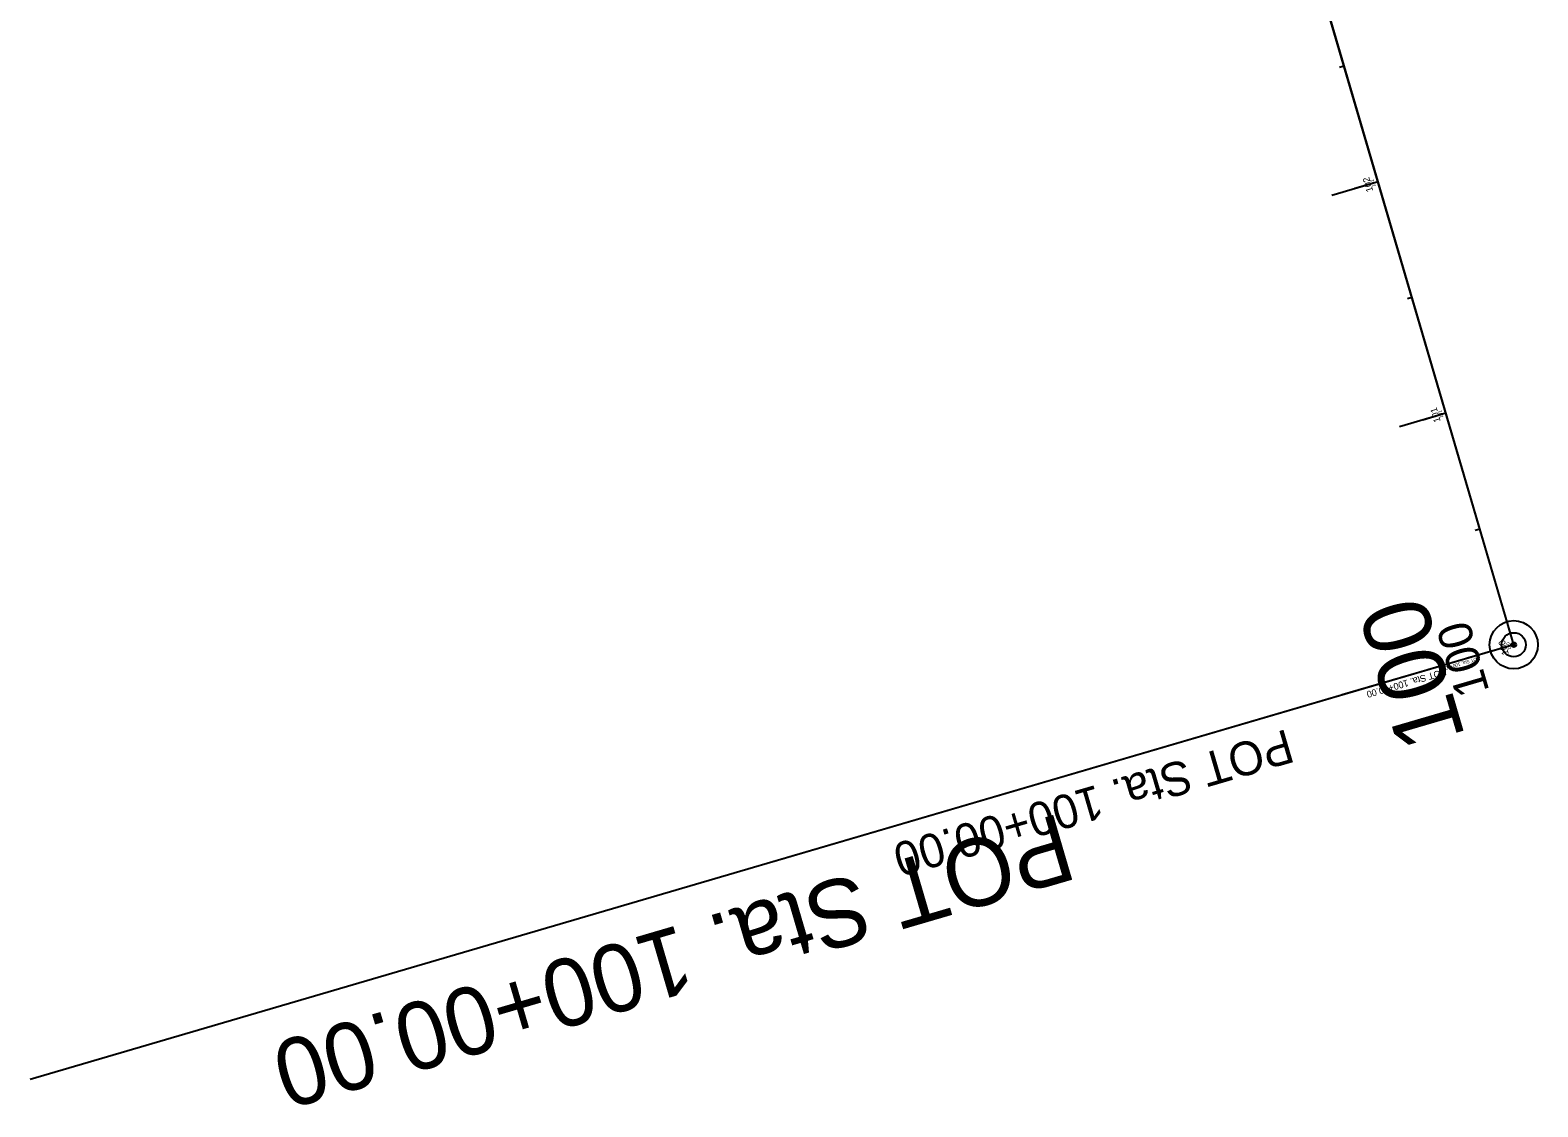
# Model space of a CAD drawing. Extents: x 1794716 to 1797874, y 325521 to 329174.
# Drawn here: x 1796186 to 1796811, y 325521 to 325968 of the extents above; entities that cross this region are included whole.
import ezdxf

# ---------------------------------------------------------------- set-up
doc = ezdxf.new("R2010")
doc.units = 0
for name, color, linetype in [('GE_P_CL_10', 7, 'Continuous'), ('GE_P_CL_100', 7, 'Continuous'), ('GE_P_CL_20', 7, 'Continuous'), ('GE_P_CL_200', 7, 'Continuous'), ('GE_P_CL_25', 7, 'Continuous'), ('RW_X_CL_20', 7, 'Continuous')]:
    doc.layers.add(name, color=color, linetype=linetype)

msp = doc.modelspace()

# ---------------------------------------------------------------- linework, layer by layer
at = {"layer": 'GE_P_CL_10'}
for p, q in [((1796800.73, 325712.87), (1796269.93, 327524.51)), ((1796730.44, 325952.78), (1796729.48, 325952.5)), ((1796744.5, 325904.8), (1796743.54, 325904.52)), ((1796758.55, 325856.82), (1796757.6, 325856.54)), ((1796772.61, 325808.84), (1796771.65, 325808.55)), ((1796786.67, 325760.85), (1796785.71, 325760.57)), ((1796800.25, 325712.73), (1796765.18, 325702.45)), ((1796800.73, 325712.87), (1796799.77, 325712.59))]:
    msp.add_line(p, q, dxfattribs=at)
msp.add_circle((1796800.73, 325712.87), 0.5, dxfattribs=at)
at = {"layer": 'GE_P_CL_100'}
for p, q in [((1796800.73, 325712.87), (1796269.93, 327524.51)), ((1796744.5, 325904.8), (1796734.9, 325901.99)), ((1796772.61, 325808.84), (1796763.02, 325806.02)), ((1796800.73, 325712.87), (1796791.13, 325710.06)), ((1796795.93, 325711.46), (1796493.17, 325622.76))]:
    msp.add_line(p, q, dxfattribs=at)
msp.add_circle((1796800.73, 325712.87), 5, dxfattribs=at)
at = {"layer": 'GE_P_CL_20'}
for p, q in [((1796800.73, 325712.87), (1796269.93, 327524.51)), ((1796730.44, 325952.78), (1796728.52, 325952.22)), ((1796744.5, 325904.8), (1796742.58, 325904.24)), ((1796758.55, 325856.82), (1796756.64, 325856.26)), ((1796772.61, 325808.84), (1796770.69, 325808.27)), ((1796786.67, 325760.85), (1796784.75, 325760.29)), ((1796800.73, 325712.87), (1796798.81, 325712.31))]:
    msp.add_line(p, q, dxfattribs=at)
msp.add_circle((1796800.73, 325712.87), 1, dxfattribs=at)
at = {"layer": 'GE_P_CL_200'}
for p, q in [((1796800.73, 325712.87), (1796269.93, 327524.51)), ((1796744.5, 325904.8), (1796725.3, 325899.18)), ((1796772.61, 325808.84), (1796753.42, 325803.21)), ((1796800.73, 325712.87), (1796781.54, 325707.25)), ((1796791.13, 325710.06), (1796185.61, 325532.64))]:
    msp.add_line(p, q, dxfattribs=at)
msp.add_circle((1796800.73, 325712.87), 10, dxfattribs=at)
at = {"layer": 'GE_P_CL_25'}
msp.add_line((1796799.77, 325712.59), (1796729.62, 325692.04), dxfattribs=at)
at = {"layer": 'RW_X_CL_20'}
msp.add_lwpolyline([(1796800.73, 325712.87), (1796269.93, 327524.51)], dxfattribs=at)

# ---------------------------------------------------------------- texts
at = {"layer": 'GE_P_CL_10'}
for s, rotation, p in [('102', 106.33034, (1796743.49, 325902.92)), ('101', 106.33034, (1796771.54, 325807.17)), ('100', 106.33034, (1796799.73, 325710.95)), ('POT Sta. 100+00.00', 196.33034, (1796786.53, 325707.98))]:
    msp.add_text(s, height=1.4, rotation=rotation, dxfattribs=at).set_placement(p)
at = {"layer": 'GE_P_CL_100'}
for s, rotation, p in [('100', 106.33034, (1796790.72, 325693.69)), ('POT Sta. 100+00.00', 196.33034, (1796706.73, 325678.04))]:
    msp.add_text(s, height=14, rotation=rotation, dxfattribs=at).set_placement(p)
at = {"layer": 'GE_P_CL_20'}
for s, p in [('102', (1796742.48, 325901.03)), ('101', (1796770.46, 325805.51)), ('100', (1796798.73, 325709.03))]:
    msp.add_text(s, height=2.8, rotation=106.33034, dxfattribs=at).set_placement(p)
at = {"layer": 'GE_P_CL_200'}
for s, rotation, p in [('100', 106.33034, (1796780.71, 325674.51)), ('POT Sta. 100+00.00', 196.33034, (1796612.74, 325643.2))]:
    msp.add_text(s, height=28, rotation=rotation, dxfattribs=at).set_placement(p)
at = {"layer": 'GE_P_CL_25'}
msp.add_text('POT Sta. 100+00.00', height=2.8, rotation=196.33034, dxfattribs=at).set_placement((1796772.33, 325703.09))

doc.saveas('drawing.dxf')
